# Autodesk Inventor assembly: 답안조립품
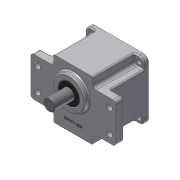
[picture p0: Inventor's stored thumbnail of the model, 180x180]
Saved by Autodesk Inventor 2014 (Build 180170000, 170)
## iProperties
Created: 2014-12
Part Number: 답안조립품
Document SubType Name: Assembly
Designer: MYHOME
Author: MYHOME
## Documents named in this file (12)
- C:\Documents and Settings\MYHOME\바탕 화면\이혜림\답안조립품.iam
- C:\Documents and Settings\MYHOME\바탕 화면\이혜림\본체.ipt
- C:\Documents and Settings\MYHOME\바탕 화면\이혜림\오일실 17x32x8.ipt
- C:\Documents and Settings\MYHOME\바탕 화면\이혜림\베어링 6003.ipt
- 베어링 6003.ipt
- C:\Documents and Settings\MYHOME\바탕 화면\이혜림\베어링 608.ipt
- 베어링 608.ipt
- C:\Documents and Settings\MYHOME\바탕 화면\이혜림\서브축.ipt
- C:\Documents and Settings\MYHOME\바탕 화면\이혜림\메인축.ipt
- C:\Documents and Settings\MYHOME\바탕 화면\이혜림\커버.ipt
- C:\Documents and Settings\MYHOME\바탕 화면\이혜림\오일실 8x22x7.ipt
- C:\Documents and Settings\MYHOME\바탕 화면\이혜림\M4x0.5x16.ipt
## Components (4 placed, 1 different names)
1. M4x0.5x12:1
2. M4x0.5x12:2
3. M4x0.5x12:3
4. M4x0.5x12:4
